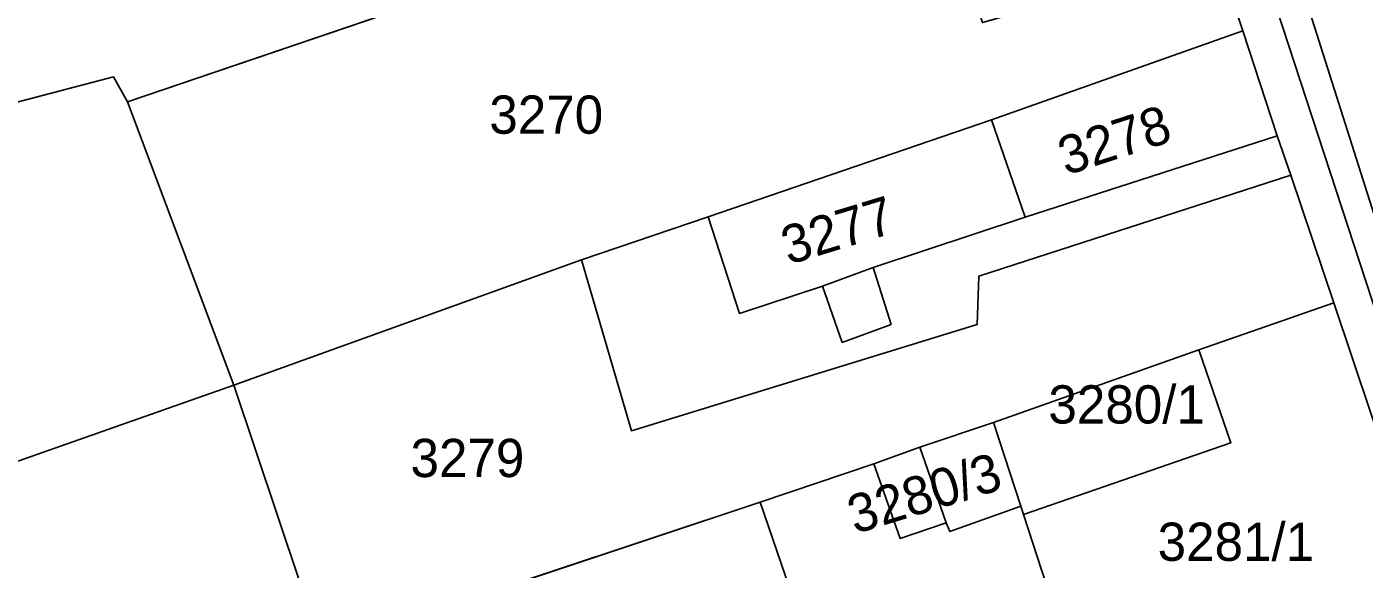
# Model space of a CAD drawing. Extents: x -262657 to -261595, y -1238015 to -1237156.
# Drawn here: x -261809.5 to -261739.6, y -1237876.6 to -1237848.2 of the extents above; entities that cross this region are included whole.
import ezdxf

# ---------------------------------------------------------------- set-up
doc = ezdxf.new("R2010")
doc.units = 0
for name, color, linetype in [('body_kn', 7, 'Continuous'), ('kladpar_druhypozemkov', 7, 'Continuous'), ('kladpar_hranice', 7, 'Continuous'), ('kladpar_parcelnecisla', 7, 'Continuous'), ('kladpar_plochy', 7, 'Continuous'), ('zappar_hrandruhpozemk', 7, 'Continuous')]:
    doc.layers.add(name, color=color, linetype=linetype)

msp = doc.modelspace()

# ---------------------------------------------------------------- linework, layer by layer
at = {"layer": 'body_kn'}
for p, q in [((-261745.94, -1237848.45), (-261745.94, -1237848.45)), ((-261745.94, -1237848.45), (-261745.94, -1237848.45)), ((-261804.96, -1237850.86), (-261804.96, -1237850.86)), ((-261804.23, -1237852.16), (-261804.23, -1237852.16)), ((-261759.07, -1237853.1), (-261759.07, -1237853.1)), ((-261744.14, -1237853.94), (-261744.14, -1237853.94)), ((-261744.14, -1237853.94), (-261744.14, -1237853.94)), ((-261743.44, -1237855.99), (-261743.44, -1237855.99)), ((-261773.89, -1237858.17), (-261773.89, -1237858.17)), ((-261773.89, -1237858.17), (-261773.89, -1237858.17)), ((-261757.31, -1237858.19), (-261757.31, -1237858.19)), ((-261780.5, -1237860.43), (-261780.5, -1237860.43)), ((-261765.27, -1237860.82), (-261765.27, -1237860.82)), ((-261759.74, -1237861.28), (-261759.74, -1237861.28)), ((-261767.91, -1237861.79), (-261767.91, -1237861.79)), ((-261767.91, -1237861.79), (-261767.91, -1237861.79)), ((-261741.18, -1237862.67), (-261741.18, -1237862.67)), ((-261772.25, -1237863.22), (-261772.25, -1237863.22)), ((-261764.32, -1237863.8), (-261764.32, -1237863.8)), ((-261759.82, -1237863.8), (-261759.82, -1237863.8)), ((-261766.88, -1237864.75), (-261766.88, -1237864.75)), ((-261748.24, -1237865.13), (-261748.24, -1237865.13)), ((-261798.67, -1237866.97), (-261798.67, -1237866.97)), ((-261758.97, -1237868.92), (-261758.97, -1237868.92)), ((-261758.97, -1237868.92), (-261758.97, -1237868.92)), ((-261777.9, -1237869.36), (-261777.9, -1237869.36)), ((-261762.82, -1237870.21), (-261762.82, -1237870.21)), ((-261762.82, -1237870.21), (-261762.82, -1237870.21)), ((-261746.57, -1237869.99), (-261746.57, -1237869.99)), ((-261765.22, -1237871.09), (-261765.22, -1237871.09)), ((-261771.16, -1237873.1), (-261771.16, -1237873.1)), ((-261771.16, -1237873.1), (-261771.16, -1237873.1)), ((-261757.55, -1237873.3), (-261757.55, -1237873.3)), ((-261757.55, -1237873.3), (-261757.55, -1237873.3)), ((-261757.41, -1237873.74), (-261757.41, -1237873.74)), ((-261761.44, -1237874.17), (-261761.44, -1237874.17)), ((-261761.26, -1237874.63), (-261761.26, -1237874.63)), ((-261763.85, -1237874.99), (-261763.85, -1237874.99))]:
    msp.add_line(p, q, dxfattribs=at)
at = {"layer": 'kladpar_druhypozemkov'}
for p, q in [((-261782.24, -1237851.22), (-261782.24, -1237851.22)), ((-261753.09, -1237853.46), (-261753.09, -1237853.46)), ((-261767.26, -1237857.49), (-261767.26, -1237857.49)), ((-261751.31, -1237867.1), (-261751.31, -1237867.1)), ((-261785.99, -1237869.09), (-261785.99, -1237869.09)), ((-261761.35, -1237871.39), (-261761.35, -1237871.39)), ((-261746.46, -1237874.41), (-261746.46, -1237874.41))]:
    msp.add_line(p, q, dxfattribs=at)
at = {"layer": 'kladpar_hranice'}
for points in [[(-261731.65, -1237875.83), (-261726.84, -1237893.01), (-261731.63, -1237894.96), (-261731.03, -1237893.79), (-261730.38, -1237891.71), (-261730.51, -1237889.08), (-261753.79, -1237817.84), (-261751.8, -1237817.14), (-261748.6, -1237826.63), (-261747.05, -1237832.91), (-261737.93, -1237861.7), (-261731.65, -1237875.83)], [(-261730.51, -1237889.08), (-261730.38, -1237891.71), (-261731.03, -1237893.79), (-261731.63, -1237894.96), (-261733.49, -1237895.72), (-261732.32, -1237889.37), (-261734.52, -1237882.73), (-261736.31, -1237877.23), (-261741.18, -1237862.67), (-261743.44, -1237855.99), (-261744.14, -1237853.94), (-261745.94, -1237848.45), (-261747.24, -1237844.54), (-261747.83, -1237842.54), (-261750.68, -1237833.95), (-261755.63, -1237818.43), (-261753.79, -1237817.84), (-261730.51, -1237889.08)], [(-261755.63, -1237818.43), (-261750.68, -1237833.95), (-261752.22, -1237834.48), (-261760.3, -1237837.27), (-261775.64, -1237842.43), (-261804.23, -1237852.16), (-261804.96, -1237850.86), (-261825.16, -1237856.15), (-261825.08, -1237840.58), (-261809.58, -1237835.59), (-261789.12, -1237829.1), (-261755.63, -1237818.43)], [(-261747.24, -1237844.54), (-261745.94, -1237848.45), (-261759.07, -1237853.1), (-261773.89, -1237858.17), (-261780.5, -1237860.43), (-261798.67, -1237866.97), (-261804.23, -1237852.16), (-261775.64, -1237842.43), (-261773.54, -1237847.41), (-261760.92, -1237843.86), (-261759.55, -1237848.02), (-261747.24, -1237844.54)], [(-261745.94, -1237848.45), (-261744.14, -1237853.94), (-261757.31, -1237858.19), (-261759.07, -1237853.1), (-261745.94, -1237848.45)], [(-261825.16, -1237856.15), (-261804.96, -1237850.86), (-261804.23, -1237852.16), (-261798.67, -1237866.97), (-261836.71, -1237880.35), (-261846.62, -1237863.53), (-261844.94, -1237862.93), (-261825.16, -1237856.15)], [(-261744.14, -1237853.94), (-261743.44, -1237855.99), (-261759.74, -1237861.28), (-261759.82, -1237863.8), (-261777.9, -1237869.36), (-261780.5, -1237860.43), (-261773.89, -1237858.17), (-261759.07, -1237853.1), (-261757.31, -1237858.19), (-261744.14, -1237853.94)], [(-261771.16, -1237873.1), (-261794.07, -1237880.71), (-261798.67, -1237866.97), (-261780.5, -1237860.43), (-261777.9, -1237869.36), (-261759.82, -1237863.8), (-261759.74, -1237861.28), (-261743.44, -1237855.99), (-261741.18, -1237862.67), (-261748.24, -1237865.13), (-261758.97, -1237868.92), (-261762.82, -1237870.21), (-261765.22, -1237871.09), (-261771.16, -1237873.1)], [(-261736.31, -1237877.23), (-261743.11, -1237879.52), (-261751.96, -1237882.49), (-261754.31, -1237883.27), (-261757.41, -1237873.74), (-261746.57, -1237869.99), (-261748.24, -1237865.13), (-261741.18, -1237862.67), (-261736.31, -1237877.23)], [(-261758.97, -1237868.92), (-261748.24, -1237865.13), (-261746.57, -1237869.99), (-261757.41, -1237873.74), (-261757.55, -1237873.3), (-261758.97, -1237868.92)], [(-261794.07, -1237880.71), (-261813.88, -1237887.48), (-261836.71, -1237895.38), (-261842.22, -1237882.31), (-261836.71, -1237880.35), (-261798.67, -1237866.97), (-261794.07, -1237880.71)], [(-261757.55, -1237873.3), (-261761.26, -1237874.63), (-261761.44, -1237874.17), (-261763.85, -1237874.99), (-261765.22, -1237871.09), (-261762.82, -1237870.21), (-261758.97, -1237868.92), (-261757.55, -1237873.3)], [(-261757.55, -1237873.3), (-261757.41, -1237873.74), (-261754.31, -1237883.27), (-261758.16, -1237884.5), (-261766.33, -1237887.24), (-261771.16, -1237873.1), (-261765.22, -1237871.09), (-261763.85, -1237874.99), (-261761.44, -1237874.17), (-261761.26, -1237874.63), (-261757.55, -1237873.3)], [(-261794.07, -1237880.71), (-261771.16, -1237873.1), (-261766.33, -1237887.24), (-261764.24, -1237893.64), (-261761.54, -1237901.92), (-261760.66, -1237904.62), (-261774.74, -1237909.35)]]:
    msp.add_lwpolyline(points, dxfattribs=at)
at = {"layer": 'kladpar_plochy'}
for p, q in [((-261775.64, -1237842.43), (-261804.23, -1237852.16)), ((-261804.96, -1237850.86), (-261825.16, -1237856.15)), ((-261804.23, -1237852.16), (-261804.96, -1237850.86)), ((-261794.07, -1237880.71), (-261771.16, -1237873.1)), ((-261771.16, -1237873.1), (-261766.33, -1237887.24))]:
    msp.add_line(p, q, dxfattribs=at)
for points in [[(-261731.65, -1237875.83), (-261726.84, -1237893.01), (-261731.63, -1237894.96), (-261731.03, -1237893.79), (-261730.38, -1237891.71), (-261730.51, -1237889.08), (-261753.79, -1237817.84), (-261751.8, -1237817.14), (-261748.6, -1237826.63), (-261747.05, -1237832.91), (-261737.93, -1237861.7)], [(-261730.51, -1237889.08), (-261730.38, -1237891.71), (-261731.03, -1237893.79), (-261731.63, -1237894.96), (-261733.49, -1237895.72), (-261732.32, -1237889.37), (-261734.52, -1237882.73), (-261736.31, -1237877.23), (-261741.18, -1237862.67), (-261743.44, -1237855.99), (-261744.14, -1237853.94), (-261745.94, -1237848.45), (-261747.24, -1237844.54), (-261747.83, -1237842.54), (-261750.68, -1237833.95), (-261755.63, -1237818.43), (-261753.79, -1237817.84)], [(-261747.24, -1237844.54), (-261745.94, -1237848.45), (-261759.07, -1237853.1), (-261773.89, -1237858.17), (-261780.5, -1237860.43), (-261798.67, -1237866.97), (-261804.23, -1237852.16), (-261775.64, -1237842.43), (-261773.54, -1237847.41), (-261760.92, -1237843.86), (-261759.55, -1237848.02)], [(-261745.94, -1237848.45), (-261744.14, -1237853.94), (-261757.31, -1237858.19), (-261759.07, -1237853.1)], [(-261825.16, -1237856.15), (-261804.96, -1237850.86), (-261804.23, -1237852.16), (-261798.67, -1237866.97), (-261836.71, -1237880.35), (-261846.62, -1237863.53), (-261844.94, -1237862.93)], [(-261744.14, -1237853.94), (-261743.44, -1237855.99), (-261759.74, -1237861.28), (-261759.82, -1237863.8), (-261777.9, -1237869.36), (-261780.5, -1237860.43), (-261773.89, -1237858.17), (-261759.07, -1237853.1), (-261757.31, -1237858.19)], [(-261771.16, -1237873.1), (-261794.07, -1237880.71), (-261798.67, -1237866.97), (-261780.5, -1237860.43), (-261777.9, -1237869.36), (-261759.82, -1237863.8), (-261759.74, -1237861.28), (-261743.44, -1237855.99), (-261741.18, -1237862.67), (-261748.24, -1237865.13), (-261758.97, -1237868.92), (-261762.82, -1237870.21), (-261765.22, -1237871.09)], [(-261736.31, -1237877.23), (-261743.11, -1237879.52), (-261751.96, -1237882.49), (-261754.31, -1237883.27), (-261757.41, -1237873.74), (-261746.57, -1237869.99), (-261748.24, -1237865.13), (-261741.18, -1237862.67)], [(-261758.97, -1237868.92), (-261748.24, -1237865.13), (-261746.57, -1237869.99), (-261757.41, -1237873.74), (-261757.55, -1237873.3)], [(-261794.07, -1237880.71), (-261813.88, -1237887.48), (-261836.71, -1237895.38), (-261842.22, -1237882.31), (-261836.71, -1237880.35), (-261798.67, -1237866.97)], [(-261757.55, -1237873.3), (-261761.26, -1237874.63), (-261761.44, -1237874.17), (-261763.85, -1237874.99), (-261765.22, -1237871.09), (-261762.82, -1237870.21), (-261758.97, -1237868.92)], [(-261757.55, -1237873.3), (-261757.41, -1237873.74), (-261754.31, -1237883.27), (-261758.16, -1237884.5), (-261766.33, -1237887.24), (-261771.16, -1237873.1), (-261765.22, -1237871.09), (-261763.85, -1237874.99), (-261761.44, -1237874.17), (-261761.26, -1237874.63)]]:
    msp.add_lwpolyline(points, close=True, dxfattribs=at)
at = {"layer": 'zappar_hrandruhpozemk'}
for p, q in [((-261767.91, -1237861.79), (-261765.27, -1237860.82)), ((-261766.88, -1237864.75), (-261764.32, -1237863.8)), ((-261762.82, -1237870.21), (-261761.44, -1237874.17))]:
    msp.add_line(p, q, dxfattribs=at)
for points in [[(-261773.89, -1237858.17), (-261772.25, -1237863.22), (-261767.91, -1237861.79), (-261766.88, -1237864.75)], [(-261764.32, -1237863.8), (-261765.27, -1237860.82), (-261757.31, -1237858.19)]]:
    msp.add_lwpolyline(points, dxfattribs=at)

# ---------------------------------------------------------------- texts
at = {"layer": 'kladpar_parcelnecisla'}
for s, p in [('3270', (-261785.323, -1237853.83)), ('3280/1', (-261756.103, -1237868.98)), ('3279', (-261789.442, -1237871.78)), ('3281/1', (-261750.392, -1237876.16))]:
    msp.add_text(s, height=2, dxfattribs=at).set_placement(p)
for s, rotation, p in [('3278', 18, (-261755.186, -1237856.023)), ('3277', 17, (-261769.682, -1237860.693)), ('3280/3', 17, (-261766.215, -1237874.768))]:
    msp.add_text(s, height=2, rotation=rotation, dxfattribs=at).set_placement(p)

doc.saveas('drawing.dxf')
